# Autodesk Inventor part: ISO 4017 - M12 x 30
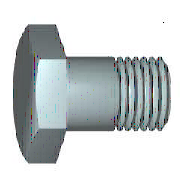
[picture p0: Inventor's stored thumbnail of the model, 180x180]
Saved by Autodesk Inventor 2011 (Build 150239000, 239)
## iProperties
Created: 2009-02
Part Number: ISO 4017 - M12 x 30
Material: Stainless Steel, 440C
Description: Hexagon head screws
Document SubType Name: Modeling
Standard: ISO 4017
Designer: V.de Jong
Standard Revision: Third edition 1999-08-15
Standards Organization: ISO
Language: en-US
Size Designation: M12 x 30
Categories: <MemberInstance><Categories><Category DisplayName="Fasteners" InternalName="e4da775c-781d-43d5-af7c-5136215cf5a6" Mnemonic="FSTN"><Category DisplayName="Bolts"
Density: 7.75 g/cm^3
Mass: 42.1026 g
Surface Area: 21.1539 cm^2
Volume: 5.43259 cm^3
IsCustomPart: 0
Author: V.de Jong
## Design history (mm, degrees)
body "Solid1"
workplane "Work Plane1"
revolve "Body" stored, may be unused: angle "d12" = 90 deg
sketch "Sketch2"
  geometry: L1 (0, 10.392)-(9, 5.196); L2 (9, 5.196)-(9, -5.196); L3 (9, -5.196)-(0, -10.392); L4 (0, -10.392)-(-9, -5.196); L5 (-9, -5.196)-(-9, 5.196); L6 (-9, 5.196)-(0, 10.392); 2 further points
  constraints: 12 end point, 1 coincident, 1 vertical, 11 other
  dimensions: "d11" = 18 distance between parallel lines of L5 L2 (= SW)
extrude "Head" join sketch "Sketch2" distance "d3" = 6.9 (= KOH - SD); taper "d4" = 0 deg
revolve "Chamfer1" stored, may be unused: angle "d21" = 90 deg
feature "Thread" dims "d15" = 24.7 (= GEL), "d16" = 0
chamfer "Chamfer2" distance "d6" = 1.07354 (= -0.5 x SPD + 0.5 x GD); stored, may be unused: second distance "d7" = 1.07364 (computed from GUL), angle "d55" = 45 deg
sketch "Sketch1"
  geometry: L1 (0, 8.315)-(0, 6); L2 (5.3, 6)-(30, 6); L3 (30, 6)-(30, 0); L4 (30, 0)-(-0.6, 0); L5 (-6.72, 0)-(36.12, 0) reference; L6 (-0.6, 0)-(-0.6, 8.315); L7 (-0.6, 8.315)-(0, 8.315); L8 (5.3, 6)-(4.226, 6); L9 (4.226, 6)-(0, 6); L10 (0, -1.663)-(0, 9.978) reference
  constraints: 16 end point, 2 collinear, 2 perpendicular, 1 parallel
  dimensions: "d0" = 30 distance between parallel lines of L3 L1 (= NLG); "d1" = 24.7 distance from line of L2.start L3 (= GEL); "d2" = 12 diameter of L2 L4 (= GD); "d9" = 0.6001 distance between parallel lines of L6 L1 (computed from SD); "d10" = 16.63 diameter of L7 L4 (= SD2); "d13" = 1.07364 distance of L2.start L8.end (computed from GAL); "d14" = 12 diameter of L9 L4 (= BDM)
sketch "Sketch4"
  geometry: L1 (-7.5, 9)-(-7.5, 10.392); L2 (-7.5, 10.392)-(-6.696, 10.392); L3 (-6.696, 10.392)-(-7.5, 9); L4 (-8.88, 0)-(0.78, 0) reference; L5 (-0.6, 10.392)-(-7.5, 10.392) reference; L6 (-7.5, 5.196)-(-7.5, 10.392) reference
  constraints: 6 end point, 2 collinear, 1 perpendicular, 1 vertical
  dimensions: "d5" = 30 deg angle of L3 L1 (= ANG1); "d19" = 18 diameter of L1.start L4 (= SW0)
other parameters: "NLG" = 30 [user parameter; used in 1 equation term], "GD" = 12 (= NND) [user parameter; used in 2 equation terms], "BDM" = 12 (= NND) [user parameter; used in 1 equation term], "KOH" = 7.5 [user parameter; used in 1 equation term], "GEL" = 24.7 [user parameter; used in 2 equation terms], "SW" = 18 [user parameter; used in 2 equation terms], "SW0" = 18 (= SW) [user parameter; used in 1 equation term], "SPD" = 9.85293 (= NND - 1.2269 x PTC) [user parameter; used in 1 equation term], "SD2" = 16.63 [user parameter; used in 2 equation terms], "SD" = 0.6 [user parameter; used in 2 equation terms], "ANG1" = 30 deg [user parameter; used in 1 equation term], "GAL" = 1.07354 (= 0.61345 x PTC) [user parameter; used in 1 equation term], "GUL" = 1.07354 (= 0.61345 x PTC) [user parameter; used in 1 equation term], "d8" = 0, "RR" = 0.6 [user parameter], "d57" = 0, "d58" = 0, "TPU" = 5.71429 (computed from PTC) [user parameter], "GD1" = 9.85293 (= THREADDIA - 1.2269 x PTC) [user parameter], "THREADDIA" = 12 [user parameter; used in 1 equation term], "SDH" = 16.63 (= SD2) [user parameter], "SDHG" = 5.3 [user parameter], "TOA" = 30 deg [user parameter], "PTC" = 1.75 [user parameter; used in 5 equation terms], "NND" = 12 [user parameter; used in 3 equation terms], "E0" = 20.79 [user parameter]
